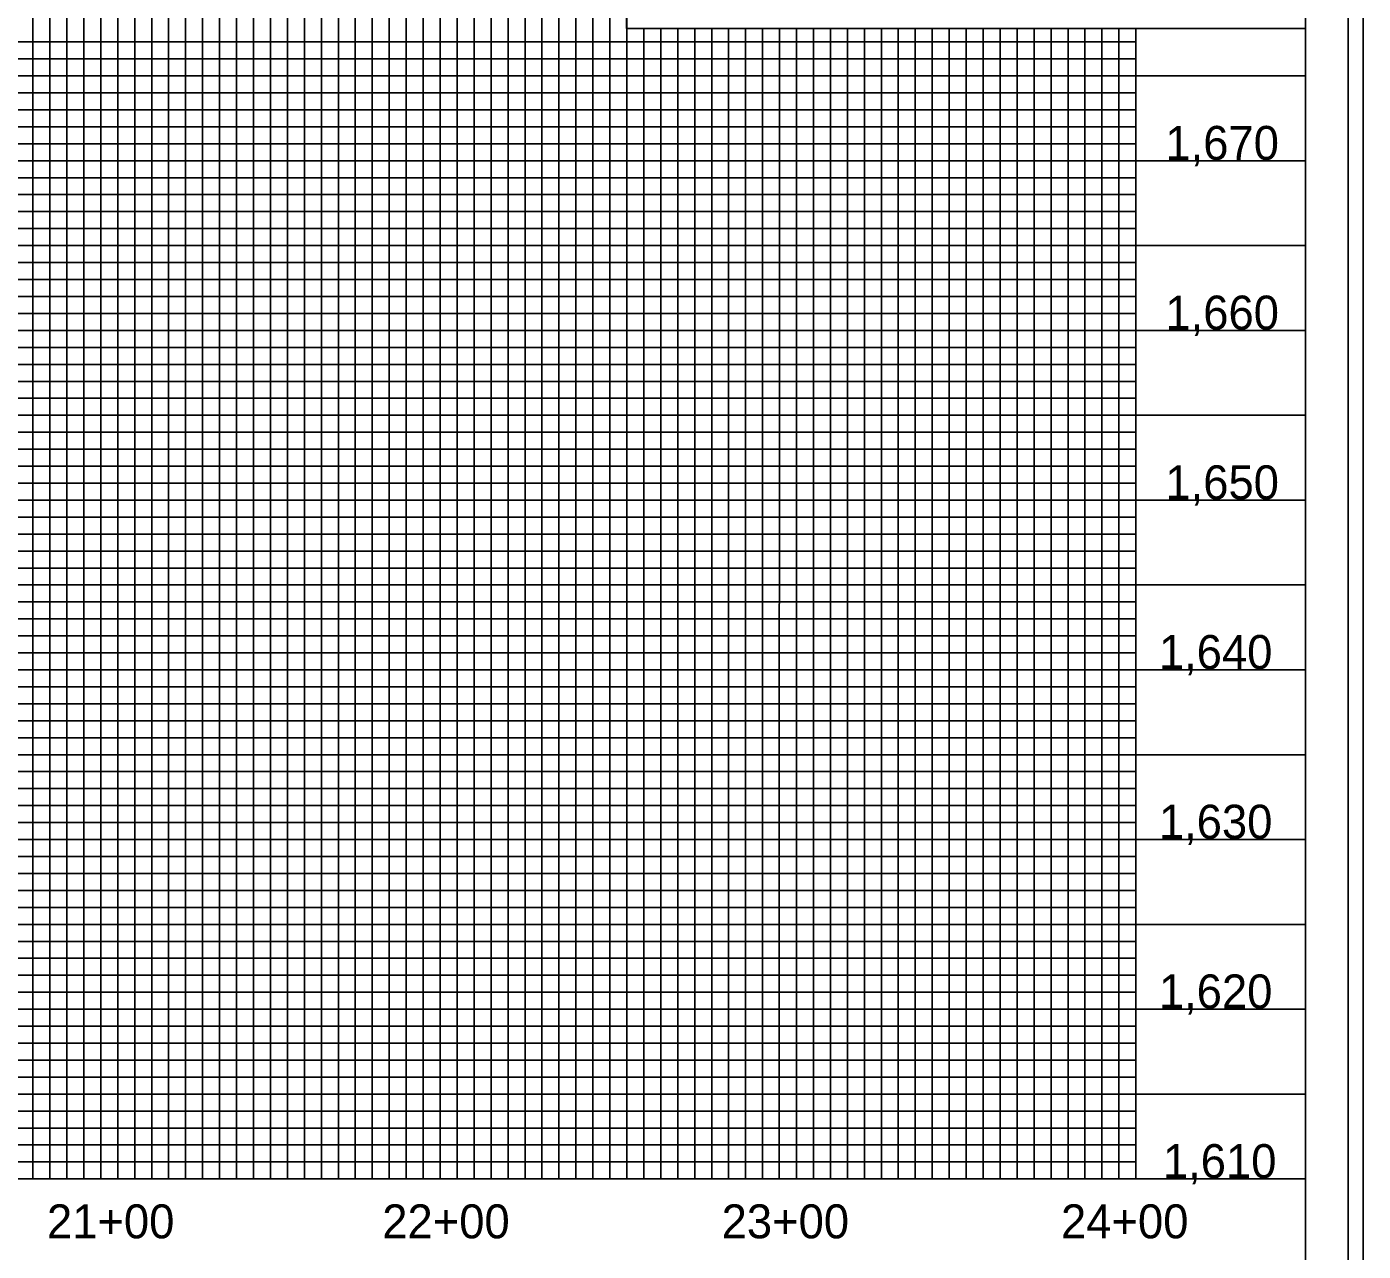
# Model space of a CAD drawing. Extents: x 497599 to 513368, y 404140 to 482942.
# Drawn here: x 506981.9 to 507375.7, y 439314.8 to 439675.6 of the extents above; entities that cross this region are included whole.
import ezdxf

# ---------------------------------------------------------------- set-up
doc = ezdxf.new("R2010")
doc.units = 0
for name, color, linetype in [('Exist Vertical Profile Vertical Axis Label', 7, 'Continuous'), ('Sheet DOT Grid CELL', 7, 'Continuous'), ('Sheet Layout Profile Border Port 1', 7, 'Continuous'), ('Sheet Plot Border Inside CELL', 7, 'Continuous'), ('Sheet Plot Border Outside CELL', 7, 'Continuous'), ('Sheet Profile CELL', 7, 'Continuous'), ('Sheet Profile Grid Major CELL', 7, 'Continuous'), ('Sheet Profile Grid Middle CELL', 7, 'Continuous'), ('Sheet Profile Grid Minor CELL', 7, 'Continuous'), ('Sheet Sticker Exception Certification CELL', 7, 'Continuous')]:
    doc.layers.add(name, color=color, linetype=linetype)

msp = doc.modelspace()

# ---------------------------------------------------------------- linework, layer by layer
at = {"layer": 'Sheet DOT Grid CELL'}
for p, q in [((507008.68, 439336.14), (507008.68, 439836.14)), ((507058.68, 439336.14), (507058.68, 439836.14)), ((507108.68, 439336.14), (507108.68, 439836.14)), ((507158.68, 439336.14), (507158.68, 439698.59)), ((507208.68, 439336.14), (507208.68, 439675.09)), ((507258.68, 439336.14), (507258.68, 439675.09)), ((507308.68, 439336.14), (507308.68, 439675.09)), ((507358.68, 439636.14), (505858.68, 439636.14)), ((507358.68, 439586.14), (505858.68, 439586.14)), ((507358.68, 439536.14), (505858.68, 439536.14)), ((507358.68, 439486.14), (505858.68, 439486.14)), ((507358.68, 439436.14), (505858.68, 439436.14)), ((507358.68, 439386.14), (505858.68, 439386.14))]:
    msp.add_line(p, q, dxfattribs=at)
at = {"layer": 'Sheet Layout Profile Border Port 1'}
msp.add_lwpolyline([(505908.68, 439831.14), (507158.68, 439831.14), (507158.63, 439675.09), (507308.68, 439675.09), (507308.68, 439336.14), (505908.68, 439336.14)], close=True, dxfattribs=at)
at = {"layer": 'Sheet Plot Border Inside CELL'}
msp.add_lwpolyline([(505704.68, 438783.59), (507371.18, 438783.59), (507371.18, 439838.69), (505704.68, 439838.69)], close=True, dxfattribs=at)
at = {"layer": 'Sheet Plot Border Outside CELL'}
msp.add_lwpolyline([(505691.68, 438761.14), (507375.68, 438761.14), (507375.68, 439861.14), (505691.68, 439861.14)], close=True, dxfattribs=at)
at = {"layer": 'Sheet Profile CELL'}
msp.add_line((505858.68, 439336.14), (507358.68, 439336.14), dxfattribs=at)
msp.add_lwpolyline([(507358.68, 439836.14), (505858.68, 439836.14), (505858.68, 438786.14), (507358.68, 438786.14)], close=True, dxfattribs=at)
at = {"layer": 'Sheet Profile Grid Major CELL'}
for points in [[(506708.68, 439336.14), (506758.68, 439336.14), (506758.68, 439836.14), (506808.68, 439836.14), (506808.68, 439336.14), (506858.68, 439336.14), (506858.68, 439836.14), (506908.68, 439836.14), (506908.68, 439336.14), (506958.68, 439336.14), (506958.68, 439836.14), (507008.68, 439836.14), (507008.68, 439336.14), (507058.68, 439336.14), (507058.68, 439836.14), (507108.68, 439836.14), (507108.68, 439336.14), (507158.68, 439336.14), (507158.68, 439836.14), (507184.98, 439836.14)], [(507308.68, 439675.09), (507308.68, 439336.14), (507358.68, 439336.14), (507358.68, 439686.14)], [(507208.68, 439675.09), (507208.68, 439336.14), (507258.68, 439336.14), (507258.68, 439336.14), (507258.68, 439675.09)], [(507358.68, 439636.14), (505858.68, 439636.14), (505858.68, 439586.14), (507358.68, 439586.14)], [(507358.68, 439536.14), (505858.68, 439536.14), (505858.68, 439486.14), (507358.68, 439486.14)], [(507358.68, 439436.14), (505858.68, 439436.14), (505858.68, 439436.14), (505858.68, 439386.14), (507358.68, 439386.14)]]:
    msp.add_lwpolyline(points, dxfattribs=at)
at = {"layer": 'Sheet Profile Grid Middle CELL'}
for points in [[(506683.68, 439836.14), (506733.68, 439836.14), (506733.68, 439336.14), (506783.68, 439336.14), (506783.68, 439836.14), (506833.68, 439836.14), (506833.68, 439336.14), (506883.68, 439336.14), (506883.68, 439836.14), (506933.68, 439836.14), (506933.68, 439336.14), (506983.68, 439336.14), (506983.68, 439836.14), (507033.68, 439836.14), (507033.68, 439336.14), (507083.68, 439336.14), (507083.68, 439836.14), (507133.68, 439836.14), (507133.68, 439336.14), (507183.68, 439336.14), (507183.68, 439675.09)], [(507183.68, 439598.94), (507183.68, 439336.14), (507233.68, 439336.14), (507233.68, 439675.09)], [(507233.68, 439598.94), (507233.68, 439336.14), (507283.68, 439336.14), (507283.68, 439675.09)], [(507358.68, 439661.14), (505858.68, 439661.14), (505858.68, 439611.14), (507183.68, 439611.14)], [(507183.68, 439611.14), (507358.68, 439611.14)], [(507358.68, 439561.14), (505858.68, 439561.14), (505858.68, 439511.14), (507358.68, 439511.14)], [(507358.68, 439461.14), (505858.68, 439461.14), (505858.68, 439411.14), (507358.68, 439411.14)], [(507358.68, 439361.14), (505858.68, 439361.14)]]:
    msp.add_lwpolyline(points, dxfattribs=at)
at = {"layer": 'Sheet Profile Grid Minor CELL'}
for p, q in [((505908.68, 439671.14), (507308.68, 439671.14)), ((507308.68, 439651.14), (505908.68, 439651.14)), ((505908.68, 439646.14), (507308.68, 439646.14)), ((507308.68, 439626.14), (505908.68, 439626.14)), ((505908.68, 439621.14), (507308.68, 439621.14)), ((507308.68, 439601.14), (505908.68, 439601.14)), ((505908.68, 439596.14), (507308.68, 439596.14)), ((507308.68, 439591.14), (505908.68, 439591.14)), ((505908.68, 439581.14), (507308.68, 439581.14)), ((507308.68, 439576.14), (505908.68, 439576.14)), ((505908.68, 439571.14), (507308.68, 439571.14)), ((507308.68, 439566.14), (505908.68, 439566.14)), ((505908.68, 439556.14), (507308.68, 439556.14)), ((507308.68, 439551.14), (505908.68, 439551.14)), ((505908.68, 439546.14), (507308.68, 439546.14)), ((507308.68, 439541.14), (505908.68, 439541.14)), ((505908.68, 439531.14), (507308.68, 439531.14)), ((507308.68, 439526.14), (505908.68, 439526.14)), ((505908.68, 439521.14), (507308.68, 439521.14)), ((507308.68, 439516.14), (505908.68, 439516.14)), ((505908.68, 439506.14), (507308.68, 439506.14)), ((507308.68, 439501.14), (505908.68, 439501.14)), ((505908.68, 439496.14), (507308.68, 439496.14)), ((507308.68, 439491.14), (505908.68, 439491.14)), ((505908.68, 439481.14), (507308.68, 439481.14)), ((507308.68, 439476.14), (505908.68, 439476.14)), ((505908.68, 439471.14), (507308.68, 439471.14)), ((507308.68, 439466.14), (505908.68, 439466.14)), ((505908.68, 439456.14), (507308.68, 439456.14)), ((507308.68, 439451.14), (505908.68, 439451.14)), ((507308.68, 439446.14), (505908.68, 439446.14)), ((507308.68, 439441.14), (505908.68, 439441.14)), ((505908.68, 439431.14), (507308.68, 439431.14)), ((507308.68, 439426.14), (505908.68, 439426.14)), ((505908.68, 439421.14), (507308.68, 439421.14)), ((507308.68, 439416.14), (505908.68, 439416.14)), ((505908.68, 439406.14), (507308.68, 439406.14)), ((507308.68, 439401.14), (505908.68, 439401.14)), ((505908.68, 439396.14), (507308.68, 439396.14)), ((507308.68, 439391.14), (505908.68, 439391.14)), ((505908.68, 439381.14), (507308.68, 439381.14)), ((507308.68, 439376.14), (505908.68, 439376.14)), ((505908.68, 439371.14), (507308.68, 439371.14)), ((507308.68, 439366.14), (505908.68, 439366.14)), ((505908.68, 439356.14), (507308.68, 439356.14)), ((507308.68, 439351.14), (505908.68, 439351.14)), ((505908.68, 439346.14), (507308.68, 439346.14))]:
    msp.add_line(p, q, dxfattribs=at)
for points in [[(506978.68, 439836.14), (506988.68, 439836.14), (506988.68, 439336.14), (506993.68, 439336.14), (506993.68, 439836.14), (506998.68, 439836.14), (506998.68, 439336.14), (507003.68, 439336.14), (507003.68, 439836.14), (507013.68, 439836.14), (507013.68, 439336.14), (507018.68, 439336.14), (507018.68, 439836.14), (507023.68, 439836.14), (507023.68, 439336.14), (507028.68, 439336.14), (507028.68, 439836.14), (507038.68, 439836.14), (507038.68, 439336.14), (507043.68, 439336.14), (507043.68, 439836.14), (507048.68, 439836.14), (507048.68, 439336.14)], [(507048.68, 439336.14), (507053.68, 439336.14), (507053.68, 439836.14)], [(507063.68, 439836.14), (507063.68, 439336.14), (507068.68, 439336.14), (507068.68, 439836.14)], [(507073.68, 439836.14), (507073.68, 439336.14), (507078.68, 439336.14), (507078.68, 439836.14)], [(507088.68, 439836.14), (507088.68, 439336.14), (507093.68, 439336.14), (507093.68, 439836.14)], [(507098.68, 439836.14), (507098.68, 439336.14), (507103.68, 439336.14), (507103.68, 439836.14)], [(507113.68, 439836.14), (507113.68, 439336.14), (507118.68, 439336.14), (507118.68, 439836.14)], [(507123.68, 439836.14), (507123.68, 439336.14), (507128.68, 439336.14), (507128.68, 439836.14)], [(507138.68, 439836.14), (507138.68, 439336.14), (507143.68, 439336.14), (507143.68, 439836.14)], [(507148.68, 439836.14), (507148.68, 439336.14), (507153.68, 439336.14), (507153.68, 439836.14)], [(507163.68, 439675.09), (507163.68, 439336.14), (507168.68, 439336.14), (507168.68, 439675.09)], [(507173.68, 439675.09), (507173.68, 439336.14), (507178.68, 439336.14), (507178.68, 439675.09)], [(507188.68, 439675.09), (507188.68, 439336.14), (507188.68, 439336.14), (507193.68, 439336.14), (507198.68, 439336.14), (507198.68, 439675.09)], [(507193.68, 439675.09), (507193.68, 439336.14)], [(507203.67, 439675.09), (507203.58, 439336.19), (507208.58, 439336.19), (507213.68, 439336.14), (507213.68, 439675.09)], [(507213.68, 439598.94), (507213.68, 439336.14), (507218.68, 439336.14), (507218.68, 439675.09)], [(507223.68, 439675.09), (507223.68, 439336.14), (507228.68, 439336.14), (507228.68, 439675.09)], [(507238.68, 439675.09), (507238.68, 439336.14), (507243.68, 439336.14), (507243.68, 439675.09)], [(507248.68, 439675.09), (507248.68, 439336.14), (507253.68, 439336.14), (507253.68, 439675.09)], [(507263.68, 439675.09), (507263.68, 439336.14), (507268.68, 439336.14), (507268.68, 439675.09)], [(507273.68, 439675.09), (507273.68, 439336.14), (507278.68, 439336.14), (507278.68, 439675.09)], [(507288.68, 439675.09), (507288.68, 439336.14), (507293.68, 439336.14), (507293.68, 439675.09)], [(507298.68, 439675.09), (507298.68, 439336.14), (507303.68, 439336.14), (507303.68, 439675.09)], [(507308.68, 439666.14), (505908.68, 439666.14), (505908.68, 439656.14), (507308.68, 439656.14)], [(507308.68, 439641.14), (505908.68, 439641.14), (505908.68, 439631.14), (507308.68, 439631.14)], [(507308.68, 439616.14), (505908.68, 439616.14), (505908.68, 439606.14), (507308.68, 439606.14)], [(507308.68, 439341.14), (505908.68, 439341.14)]]:
    msp.add_lwpolyline(points, dxfattribs=at)
at = {"layer": 'Sheet Sticker Exception Certification CELL'}
for p, q in [((507158.63, 439675.09), (507158.63, 439698.59)), ((507158.63, 439675.09), (507158.63, 439698.59)), ((507358.67, 439698.58), (507358.67, 439675.08)), ((507358.67, 439698.58), (507358.67, 439675.08)), ((507358.67, 439675.09), (507158.63, 439675.09)), ((507358.67, 439675.09), (507158.63, 439675.09))]:
    msp.add_line(p, q, dxfattribs=at)

# ---------------------------------------------------------------- texts
at = {"layer": 'Exist Vertical Profile Vertical Axis Label'}
for s, p in [('1,670', (507317.37, 439636.39)), ('1,660', (507317.37, 439586.39)), ('1,650', (507317.37, 439536.39)), ('1,640', (507315.44, 439486.39)), ('1,630', (507315.44, 439436.39)), ('1,620', (507315.44, 439386.39)), ('1,610', (507316.63, 439336.39)), ('21+00', (506987.81, 439318.64)), ('22+00', (507086.61, 439318.64)), ('23+00', (507186.61, 439318.64)), ('24+00', (507286.61, 439318.64))]:
    msp.add_text(s, height=10, dxfattribs=at).set_placement(p)

doc.saveas('drawing.dxf')
